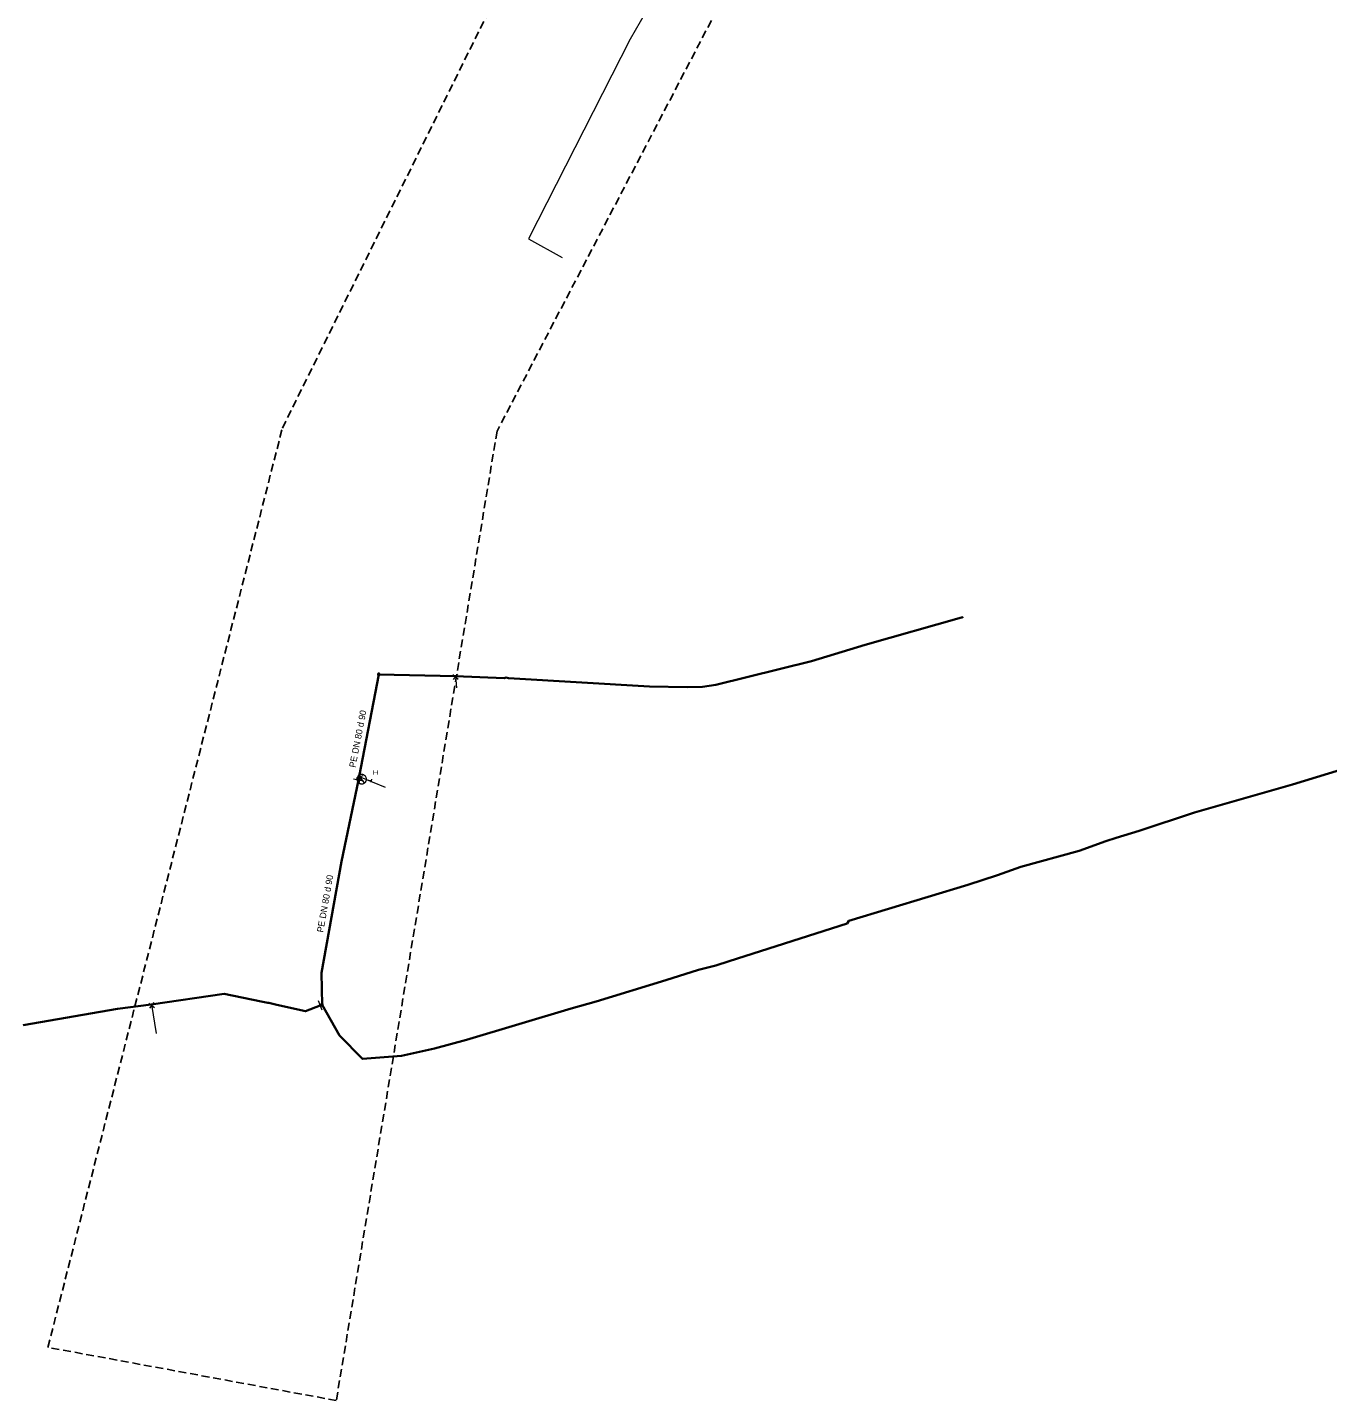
# Model space of a CAD drawing. Extents: x -743677 to -742923, y -1027084 to -1026416.
# Drawn here: x -743539.6 to -743300.4, y -1027084.2 to -1026831.6 of the extents above; entities that cross this region are included whole.
import ezdxf

# ---------------------------------------------------------------- set-up
doc = ezdxf.new("R2010")
doc.units = 0
doc.header["$LTSCALE"] = 0.48
doc.linetypes.add('MEDIUM_DASHED', pattern=[4.5, 3, -1.5])
for name, color, linetype, lineweight in [('15', 7, 'Continuous', 13), ('16', 7, 'Continuous', 35), ('20', 7, 'Continuous', 13), ('59', 7, 'Continuous', 13), ('62', 7, 'MEDIUM_DASHED', 25)]:
    doc.layers.add(name, color=color, linetype=linetype, lineweight=lineweight)
doc.layers.add('17', color=7, linetype='Continuous')

msp = doc.modelspace()

# ---------------------------------------------------------------- linework, layer by layer
at = {"layer": '15'}
for p, q in [((-743461.371, -1026950.649), (-743460.364, -1026951.474)), ((-743460.46, -1026950.563), (-743461.28, -1026951.559)), ((-743479.076, -1026969.678), (-743477.873, -1026969.18)), ((-743478.721, -1026968.834), (-743478.23, -1026970.028)), ((-743478.587, -1026970.76), (-743478.312, -1026968.918)), ((-743477.801, -1026970.27), (-743479.619, -1026969.869)), ((-743517.277, -1027011.119), (-743516.228, -1027011.89)), ((-743516.371, -1027010.985), (-743517.138, -1027012.023)), ((-743485.392, -1027012.393), (-743486.087, -1027010.665))]:
    msp.add_line(p, q, dxfattribs=at)
for points in [[(-743474.749, -1026950.61), (-743474.755, -1026950.558), (-743474.772, -1026950.508), (-743474.801, -1026950.464), (-743474.838, -1026950.427), (-743474.883, -1026950.4), (-743474.933, -1026950.383), (-743474.986, -1026950.379), (-743475.038, -1026950.386), (-743475.087, -1026950.405), (-743475.13, -1026950.434), (-743475.166, -1026950.473), (-743475.192, -1026950.518), (-743475.208, -1026950.569), (-743475.211, -1026950.621), (-743475.203, -1026950.673), (-743475.183, -1026950.722), (-743475.152, -1026950.765), (-743475.113, -1026950.799), (-743475.067, -1026950.825), (-743475.016, -1026950.839), (-743474.963, -1026950.841), (-743474.912, -1026950.831), (-743474.864, -1026950.81), (-743474.821, -1026950.779), (-743474.787, -1026950.738), (-743474.763, -1026950.692), (-743474.75, -1026950.641)], [(-743474.779, -1026950.61), (-743474.785, -1026950.561), (-743474.802, -1026950.515), (-743474.83, -1026950.475), (-743474.867, -1026950.443), (-743474.911, -1026950.421), (-743474.959, -1026950.41), (-743475.008, -1026950.41), (-743475.054, -1026950.423), (-743475.098, -1026950.447), (-743475.134, -1026950.48), (-743475.161, -1026950.521), (-743475.177, -1026950.568), (-743475.181, -1026950.617), (-743475.174, -1026950.665), (-743475.155, -1026950.71), (-743475.125, -1026950.75), (-743475.087, -1026950.781), (-743475.043, -1026950.801), (-743474.995, -1026950.811), (-743474.946, -1026950.809), (-743474.899, -1026950.794), (-743474.856, -1026950.769), (-743474.821, -1026950.735), (-743474.796, -1026950.693), (-743474.782, -1026950.646)], [(-743474.809, -1026950.61), (-743474.815, -1026950.565), (-743474.831, -1026950.523), (-743474.86, -1026950.488), (-743474.896, -1026950.461), (-743474.938, -1026950.444), (-743474.983, -1026950.439), (-743475.027, -1026950.445), (-743475.069, -1026950.464), (-743475.103, -1026950.492), (-743475.13, -1026950.529), (-743475.147, -1026950.571), (-743475.151, -1026950.616), (-743475.144, -1026950.661), (-743475.125, -1026950.702), (-743475.096, -1026950.736), (-743475.059, -1026950.762), (-743475.016, -1026950.778), (-743474.971, -1026950.781), (-743474.926, -1026950.773), (-743474.886, -1026950.753), (-743474.852, -1026950.724), (-743474.826, -1026950.686), (-743474.812, -1026950.643)], [(-743474.839, -1026950.61), (-743474.843, -1026950.569), (-743474.862, -1026950.532), (-743474.889, -1026950.501), (-743474.924, -1026950.48), (-743474.964, -1026950.469), (-743475.005, -1026950.471), (-743475.044, -1026950.484), (-743475.078, -1026950.508), (-743475.103, -1026950.54), (-743475.118, -1026950.578), (-743475.12, -1026950.619), (-743475.113, -1026950.659), (-743475.093, -1026950.695), (-743475.064, -1026950.724), (-743475.027, -1026950.743), (-743474.987, -1026950.751), (-743474.946, -1026950.747), (-743474.907, -1026950.732), (-743474.875, -1026950.706), (-743474.853, -1026950.672), (-743474.84, -1026950.633)], [(-743474.869, -1026950.61), (-743474.874, -1026950.574), (-743474.892, -1026950.542), (-743474.918, -1026950.517), (-743474.951, -1026950.502), (-743474.988, -1026950.499), (-743475.022, -1026950.507), (-743475.054, -1026950.527), (-743475.076, -1026950.555), (-743475.09, -1026950.589), (-743475.09, -1026950.626), (-743475.079, -1026950.661), (-743475.058, -1026950.69), (-743475.027, -1026950.711), (-743474.993, -1026950.721), (-743474.956, -1026950.719), (-743474.922, -1026950.705), (-743474.895, -1026950.682), (-743474.875, -1026950.65), (-743474.869, -1026950.615)], [(-743474.899, -1026950.61), (-743474.904, -1026950.579), (-743474.921, -1026950.553), (-743474.946, -1026950.536), (-743474.977, -1026950.529), (-743475.008, -1026950.533), (-743475.035, -1026950.55), (-743475.053, -1026950.574), (-743475.061, -1026950.605), (-743475.057, -1026950.635), (-743475.042, -1026950.663), (-743475.017, -1026950.682), (-743474.988, -1026950.691), (-743474.956, -1026950.688), (-743474.929, -1026950.674), (-743474.909, -1026950.65), (-743474.899, -1026950.621)], [(-743474.929, -1026950.61), (-743474.934, -1026950.586), (-743474.951, -1026950.568), (-743474.973, -1026950.559), (-743474.998, -1026950.562), (-743475.019, -1026950.576), (-743475.03, -1026950.598), (-743475.03, -1026950.623), (-743475.017, -1026950.644), (-743474.998, -1026950.658), (-743474.973, -1026950.661), (-743474.95, -1026950.652), (-743474.934, -1026950.634)], [(-743474.959, -1026950.61), (-743474.964, -1026950.595), (-743474.978, -1026950.589), (-743474.994, -1026950.593), (-743475, -1026950.607), (-743474.997, -1026950.622), (-743474.983, -1026950.631), (-743474.968, -1026950.628), (-743474.959, -1026950.616)], [(-743485.189, -1027011.4), (-743485.195, -1027011.348), (-743485.212, -1027011.298), (-743485.241, -1027011.254), (-743485.278, -1027011.217), (-743485.323, -1027011.19), (-743485.373, -1027011.173), (-743485.426, -1027011.169), (-743485.478, -1027011.176), (-743485.527, -1027011.195), (-743485.57, -1027011.224), (-743485.606, -1027011.263), (-743485.632, -1027011.308), (-743485.648, -1027011.359), (-743485.651, -1027011.411), (-743485.643, -1027011.463), (-743485.623, -1027011.512), (-743485.592, -1027011.555), (-743485.553, -1027011.589), (-743485.507, -1027011.615), (-743485.456, -1027011.629), (-743485.403, -1027011.631), (-743485.352, -1027011.621), (-743485.304, -1027011.6), (-743485.261, -1027011.569), (-743485.227, -1027011.528), (-743485.203, -1027011.482), (-743485.191, -1027011.431)], [(-743485.219, -1027011.4), (-743485.225, -1027011.351), (-743485.242, -1027011.305), (-743485.27, -1027011.265), (-743485.307, -1027011.233), (-743485.351, -1027011.211), (-743485.399, -1027011.2), (-743485.448, -1027011.2), (-743485.495, -1027011.213), (-743485.538, -1027011.237), (-743485.574, -1027011.27), (-743485.601, -1027011.311), (-743485.617, -1027011.358), (-743485.621, -1027011.407), (-743485.614, -1027011.455), (-743485.595, -1027011.5), (-743485.565, -1027011.54), (-743485.527, -1027011.571), (-743485.483, -1027011.591), (-743485.435, -1027011.601), (-743485.386, -1027011.599), (-743485.339, -1027011.584), (-743485.296, -1027011.559), (-743485.262, -1027011.525), (-743485.236, -1027011.483), (-743485.222, -1027011.436)], [(-743485.249, -1027011.4), (-743485.255, -1027011.355), (-743485.272, -1027011.313), (-743485.3, -1027011.278), (-743485.336, -1027011.251), (-743485.378, -1027011.234), (-743485.423, -1027011.229), (-743485.468, -1027011.235), (-743485.509, -1027011.254), (-743485.544, -1027011.282), (-743485.571, -1027011.319), (-743485.587, -1027011.361), (-743485.591, -1027011.406), (-743485.584, -1027011.451), (-743485.565, -1027011.492), (-743485.536, -1027011.526), (-743485.499, -1027011.552), (-743485.456, -1027011.568), (-743485.411, -1027011.571), (-743485.366, -1027011.563), (-743485.326, -1027011.543), (-743485.292, -1027011.514), (-743485.266, -1027011.476), (-743485.252, -1027011.433)], [(-743485.279, -1027011.4), (-743485.284, -1027011.359), (-743485.302, -1027011.322), (-743485.329, -1027011.291), (-743485.364, -1027011.27), (-743485.404, -1027011.259), (-743485.445, -1027011.261), (-743485.484, -1027011.274), (-743485.518, -1027011.298), (-743485.543, -1027011.33), (-743485.558, -1027011.368), (-743485.561, -1027011.409), (-743485.553, -1027011.449), (-743485.533, -1027011.485), (-743485.504, -1027011.514), (-743485.467, -1027011.533), (-743485.427, -1027011.541), (-743485.386, -1027011.537), (-743485.348, -1027011.522), (-743485.316, -1027011.496), (-743485.293, -1027011.462), (-743485.28, -1027011.423)], [(-743485.309, -1027011.4), (-743485.314, -1027011.364), (-743485.332, -1027011.332), (-743485.358, -1027011.307), (-743485.392, -1027011.292), (-743485.428, -1027011.289), (-743485.463, -1027011.297), (-743485.494, -1027011.317), (-743485.517, -1027011.345), (-743485.53, -1027011.379), (-743485.53, -1027011.416), (-743485.519, -1027011.451), (-743485.498, -1027011.48), (-743485.468, -1027011.501), (-743485.433, -1027011.511), (-743485.396, -1027011.509), (-743485.362, -1027011.495), (-743485.335, -1027011.472), (-743485.316, -1027011.44), (-743485.309, -1027011.405)], [(-743485.339, -1027011.4), (-743485.344, -1027011.369), (-743485.361, -1027011.343), (-743485.387, -1027011.326), (-743485.417, -1027011.319), (-743485.448, -1027011.323), (-743485.475, -1027011.34), (-743485.493, -1027011.364), (-743485.501, -1027011.395), (-743485.497, -1027011.425), (-743485.482, -1027011.453), (-743485.458, -1027011.472), (-743485.428, -1027011.481), (-743485.397, -1027011.478), (-743485.369, -1027011.464), (-743485.349, -1027011.44), (-743485.339, -1027011.411)], [(-743485.369, -1027011.4), (-743485.374, -1027011.376), (-743485.391, -1027011.358), (-743485.414, -1027011.349), (-743485.438, -1027011.352), (-743485.459, -1027011.366), (-743485.47, -1027011.388), (-743485.47, -1027011.413), (-743485.458, -1027011.434), (-743485.438, -1027011.448), (-743485.413, -1027011.451), (-743485.39, -1027011.442), (-743485.374, -1027011.424)], [(-743485.399, -1027011.4), (-743485.404, -1027011.385), (-743485.419, -1027011.379), (-743485.434, -1027011.383), (-743485.441, -1027011.397), (-743485.437, -1027011.412), (-743485.424, -1027011.421), (-743485.409, -1027011.418), (-743485.399, -1027011.406)]]:
    msp.add_lwpolyline(points, close=True, dxfattribs=at)
at = {"layer": '16'}
msp.add_line((-743485.42, -1027011.4), (-743485.74, -1027011.53), dxfattribs=at)
for points in [[(-743474.98, -1026950.609), (-743460.879, -1026950.96), (-743451.879, -1026951.289), (-743451.55, -1026951.199), (-743451.089, -1026951.3), (-743425.129, -1026952.82), (-743418.23, -1026952.94), (-743415.399, -1026952.92), (-743412.949, -1026952.55), (-743395.359, -1026948.14), (-743385.44, -1026945.14), (-743367.75, -1026940.149), (-743367.589, -1026940.109), (-743367.421, -1026939.999)], [(-743478.71, -1026970.07), (-743478.649, -1026969.809), (-743478.55, -1026969.399), (-743474.98, -1026950.609)], [(-743485.42, -1027011.399), (-743482.199, -1027017.079), (-743477.989, -1027021.37), (-743470.763, -1027020.798), (-743464.73, -1027019.438), (-743458.855, -1027017.833), (-743439.537, -1027012.085), (-743434.978, -1027010.8), (-743422.114, -1027006.85), (-743416.16, -1027004.997), (-743412.912, -1027004.203), (-743410.513, -1027003.399), (-743388.771, -1026996.462), (-743388.462, -1026995.96), (-743366.539, -1026989.34), (-743361.111, -1026987.539), (-743356.8, -1026986.01), (-743346.081, -1026983.048), (-743341.16, -1026981.309), (-743339.243, -1026980.679), (-743335.054, -1026979.399), (-743324.842, -1026976.011), (-743306.802, -1026970.896), (-743291.366, -1026966.144)], [(-743478.71, -1026970.07), (-743481.842, -1026985.011), (-743485.53, -1027005.539), (-743485.42, -1027011.399)], [(-743485.74, -1027011.53), (-743488.43, -1027012.6), (-743493.737, -1027011.397), (-743495.179, -1027011.07), (-743495.41, -1027011.019), (-743496.636, -1027010.768), (-743503.4, -1027009.38), (-743516.875, -1027011.352), (-743523.08, -1027012.17), (-743540.417, -1027015.168)]]:
    msp.add_lwpolyline(points, dxfattribs=at)
at = {"layer": '20'}
for p, q in [((-743477.598, -1026970.586), (-743478.639, -1026969.18)), ((-743477.242, -1026970.014), (-743476.368, -1026970.145)), ((-743476.328, -1026969.878), (-743476.408, -1026970.413))]:
    msp.add_line(p, q, dxfattribs=at)
msp.add_lwpolyline([(-743478.247, -1026970.753), (-743478.158, -1026970.762), (-743478.067, -1026970.762), (-743477.974, -1026970.751), (-743477.886, -1026970.732), (-743477.799, -1026970.703), (-743477.715, -1026970.665), (-743477.637, -1026970.618), (-743477.562, -1026970.564), (-743477.496, -1026970.501), (-743477.435, -1026970.434), (-743477.382, -1026970.359), (-743477.335, -1026970.279), (-743477.298, -1026970.195), (-743477.271, -1026970.108), (-743477.254, -1026970.018), (-743477.244, -1026969.926), (-743477.244, -1026969.835), (-743477.255, -1026969.745), (-743477.276, -1026969.655), (-743477.305, -1026969.567), (-743477.344, -1026969.485), (-743477.388, -1026969.405), (-743477.444, -1026969.332), (-743477.505, -1026969.264), (-743477.575, -1026969.203), (-743477.649, -1026969.15), (-743477.728, -1026969.106), (-743477.813, -1026969.069), (-743477.9, -1026969.041), (-743477.99, -1026969.022), (-743478.08, -1026969.015), (-743478.171, -1026969.015), (-743478.264, -1026969.025), (-743478.352, -1026969.045), (-743478.439, -1026969.074), (-743478.523, -1026969.112), (-743478.601, -1026969.159), (-743478.676, -1026969.212), (-743478.742, -1026969.275), (-743478.803, -1026969.343), (-743478.856, -1026969.418), (-743478.903, -1026969.498), (-743478.938, -1026969.582), (-743478.967, -1026969.668), (-743478.984, -1026969.759), (-743478.994, -1026969.85), (-743478.992, -1026969.942), (-743478.983, -1026970.032), (-743478.962, -1026970.122), (-743478.933, -1026970.21), (-743478.894, -1026970.292), (-743478.85, -1026970.372), (-743478.794, -1026970.445), (-743478.733, -1026970.512), (-743478.663, -1026970.573), (-743478.589, -1026970.627), (-743478.51, -1026970.671), (-743478.425, -1026970.708), (-743478.338, -1026970.735), (-743478.249, -1026970.753)], dxfattribs=at)
at = {"layer": '59'}
for p, q in [((-743460.88, -1026950.96), (-743460.67, -1026953.07)), ((-743478.55, -1026969.399), (-743473.789, -1026971.37)), ((-743478.65, -1026969.81), (-743478.119, -1026969.889)), ((-743516.78, -1027011.339), (-743515.96, -1027016.699))]:
    msp.add_line(p, q, dxfattribs=at)
msp.add_lwpolyline([(-743414.432, -1026814.469), (-743414.413, -1026814.504), (-743423.161, -1026824.075), (-743428.699, -1026833.696), (-743447.419, -1026870.437), (-743441.249, -1026873.874)], dxfattribs=at)
at = {"layer": '62'}
msp.add_lwpolyline([(-743185.331, -1026452.124), (-743185.314, -1026452.115), (-743122.624, -1026517.483), (-743128.636, -1026561.04), (-743080.591, -1026678.626), (-742988.56, -1026728.316), (-742957.099, -1026715.401), (-742922.946, -1026754.658), (-742988.389, -1026762.896), (-743109.886, -1026711.598), (-743142.114, -1026640.576), (-743238.891, -1026678.985), (-743355.253, -1026751.681), (-743402.763, -1026809.228), (-743453.197, -1026905.826), (-743482.789, -1027084.226), (-743535.862, -1027074.436), (-743492.719, -1026905.289), (-743434.421, -1026787.581), (-743381.806, -1026711.007), (-743250.543, -1026637.895), (-743166.228, -1026600.23)], close=True, dxfattribs=at)

# ---------------------------------------------------------------- texts
at = {"layer": '17'}
for rotation, p in [(79, (-743479.271, -1026967.825)), (80, (-743485.189, -1026998.159))]:
    msp.add_text('PE DN 80 d 90 ', height=1.2, rotation=rotation, dxfattribs=at).set_placement(p)
at = {"layer": '20', "width": 1.45}
msp.add_text('H ', height=0.8, dxfattribs=at).set_placement((-743476.092, -1026969.063))

doc.saveas('drawing.dxf')
